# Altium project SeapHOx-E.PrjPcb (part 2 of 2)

## Sheet Pump and Aux Ports-E.SchDoc: SeapHOx ARM Controller
size Letter; DocumentNumber: 1; Revision: E; SheetNumber: 7; SheetTotal: 7; PageSetup: Record=PageOptions¦CenterHorizontal=True¦CenterVertical=True¦PrintScale=0.94¦XCorrection=1.00¦YCorrection=1.00¦PrintKind=0¦BorderSize=5000000¦LeftOffset=0¦BottomOffset=0¦Orientation=2¦PaperLength=1000¦PaperWidth=1000¦Scale=100¦PaperSource=7¦PrintQuality=-4¦MediaType=1¦DitherType=10¦PrintScaleMode=1¦PaperKind=Letter¦PaperIndex=1
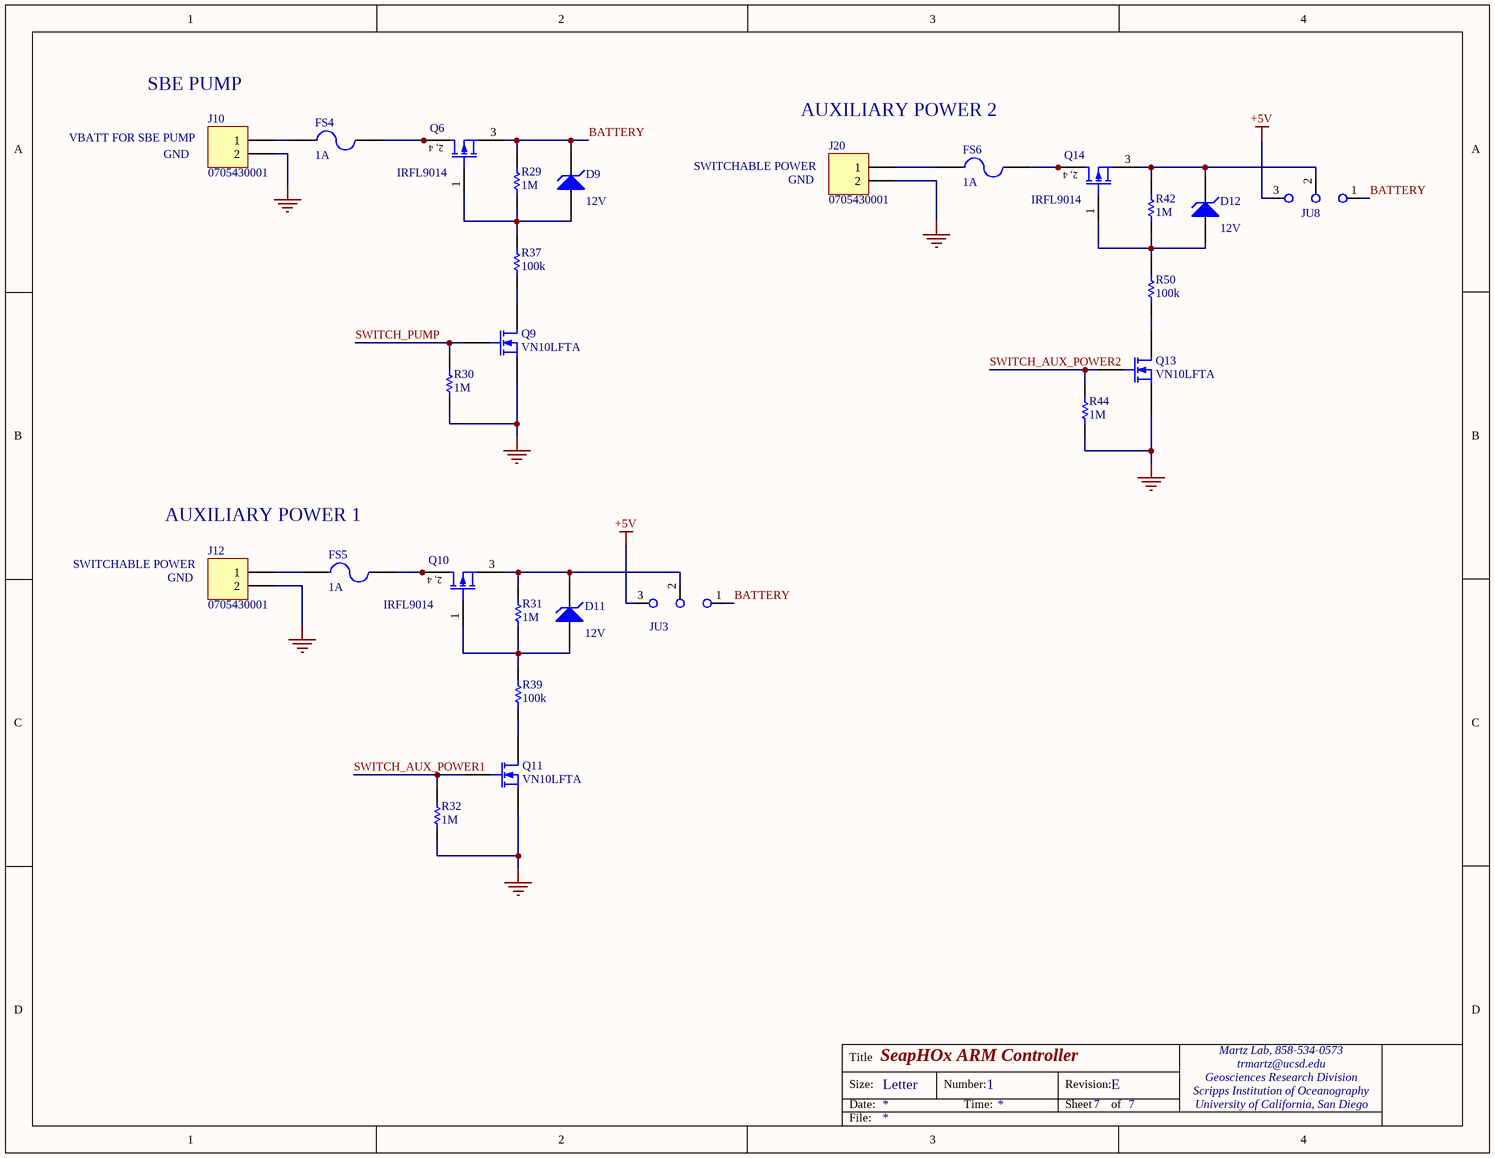
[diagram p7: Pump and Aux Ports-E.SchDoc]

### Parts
D9  12V  [SOD323F 1005]
D11  12V  [SOD323F 1005]
D12  12V  [SOD323F 1005]
FS4  Current Rating: 1A  [FUSE-NANO-SMD]  (hidden comment: 5A)
FS5  Current Rating: 1A  [FUSE-NANO-SMD]  (hidden comment: 5A)
FS6  Current Rating: 1A  [FUSE-NANO-SMD]  (hidden comment: 5A)
J10  0705430001  [70543-0001]
J12  0705430001  [70543-0001]
J20  0705430001  [70543-0001]
JU3  68000-203HLF  [Jump-3 100mil]  (value not drawn)
JU8  68000-203HLF  [Jump-3 100mil]  (value not drawn)
Q6  IRFL9014  [SOT-223]
Q9  VN10LFTA  [SOT23-3]
Q10  IRFL9014  [SOT-223]
Q11  VN10LFTA  [SOT23-3]
Q13  VN10LFTA  [SOT23-3]
Q14  IRFL9014  [SOT-223]
R29  Resistance (Ohms): 1M  [RESC0805(2012)_N]  (hidden comment: ERJ-6GEYJ105V)
R30  Resistance (Ohms): 1M  [RESC0805(2012)_N]  (hidden comment: ERJ-6GEYJ105V)
R31  Resistance (Ohms): 1M  [RESC0805(2012)_N]  (hidden comment: ERJ-6GEYJ105V)
R32  Resistance (Ohms): 1M  [RESC0805(2012)_N]  (hidden comment: ERJ-6GEYJ105V)
R37  Resistance (Ohms): 100k  [RESC0805(2012)_N]  (hidden comment: ERJ-6GEYJ104V)
R39  Resistance (Ohms): 100k  [RESC0805(2012)_N]  (hidden comment: ERJ-6GEYJ104V)
R42  Resistance (Ohms): 1M  [RESC0805(2012)_N]  (hidden comment: ERJ-6GEYJ105V)
R44  Resistance (Ohms): 1M  [RESC0805(2012)_N]  (hidden comment: ERJ-6GEYJ105V)
R50  Resistance (Ohms): 100k  [RESC0805(2012)_N]  (hidden comment: ERJ-6GEYJ104V)

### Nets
+5V: JU3.3(C3) JU8.3(C3)
BATTERY: D9.2(K) JU3.1(C1) JU8.1(C1) Q6.3(S) R29.2
GND: J10.2 J12.2 J20.2 Q9.2(S) Q11.2(S) Q13.2(S) R30.1 R32.1 R44.1
SWITCH_AUX_POWER1: Q11.1(G) R32.2
SWITCH_AUX_POWER2: Q13.1(G) R44.2
SWITCH_PUMP: Q9.1(G) R30.2
NetD9_1: D9.1(A) Q6.1(G) R29.1 R37.2
NetD11_1: D11.1(A) Q10.1(G) R31.1 R39.2
NetD11_2: D11.2(K) JU3.2(C2) Q10.3(S) R31.2
NetD12_1: D12.1(A) Q14.1(G) R42.1 R50.2
NetD12_2: D12.2(K) JU8.2(C2) Q14.3(S) R42.2
NetFS4_1: FS4.1 J10.1
NetFS4_2: FS4.2 Q6.2(D) Q6.4(D)
NetFS5_1: FS5.1 J12.1
NetFS5_2: FS5.2 Q10.2(D) Q10.4(D)
NetFS6_1: FS6.1 J20.1
NetFS6_2: FS6.2 Q14.2(D) Q14.4(D)
NetQ9_3: Q9.3(D) R37.1
NetQ11_3: Q11.3(D) R39.1
NetQ13_3: Q13.3(D) R50.1

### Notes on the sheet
- (near J10) SBE PUMP
- VBATT FOR SBE PUMP
- GND
- AUXILIARY POWER 2
- SWITCHABLE POWER
- AUXILIARY POWER 1

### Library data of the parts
D9 D11 D12 = CZRF52C12: DIODE ZENER 12V 200MW 1005; Manufacturer: Comchip Technology; Tolerance: ±5%; Current - Reverse Leakage @ Vr: 100nA @ 9V; Impedance (Max) (Zzt): 20 Ohm; Voltage - Forward (Vf) (Max) @ If: 900mV @ 10mA
FS4-FS6 = 0157001.DR: FUSE FAST 125VAC, 125VDC 1A SMD; Manufacturer: Littelfuse Inc; Fuse Type: Board Mount (Cartridge Style Excluded); Voltage Rating - AC: 125V; Breaking Capacity @ Rated Voltage: 50A; Melting I²t: 0.459; Approvals: cULus, PSE; DC Cold Resistance: 0.1537 Ohm
J10 J12 J20 = 0705430001: CONN HEADER 2POS .100 VERT GOLD; Manufacturer: Molex Inc; Connector Type: Header, Shrouded; Number of Positions: 2; Number of Positions Loaded: All; Pitch: 0.100" (2.54mm)
JU3 JU8 = 68000-203HLF: BERGSTIK II .100" SR STRAIGHT; Manufacturer: FCI; Connector Type: Header, Unshrouded; Number of Positions: 3; Number of Positions Loaded: All; Pitch: 0.100" (2.54mm)
Q6 Q10 Q14 = IRFL9014TRPBF: MOSFET P-CH 60V 1.8A SOT223; Manufacturer: Vishay Siliconix; FET Type: MOSFET P-Channel, Metal Oxide; FET Feature: Standard; Current - Continuous Drain (Id) @ 25° C: 1.8A (Tc); Rds On (Max) @ Id, Vgs: 500 mOhm @ 1.1A, 10V; Vgs(th) (Max) @ Id: 4V @ 250µA; Gate Charge (Qg) @ Vgs: 12nC @ 10V; Input Capacitance (Ciss) @ Vds: 270pF @ 25V; Power - Max: 2W
Q9 Q11 Q13 = VN10LFTA: MOSFET N-CH 60V 150MA SOT23-3; Manufacturer: Diodes Inc; FET Type: MOSFET N-Channel, Metal Oxide; FET Feature: Standard; Current - Continuous Drain (Id) @ 25° C: 150mA (Ta); Rds On (Max) @ Id, Vgs: 5 Ohm @ 500mA, 10V; Vgs(th) (Max) @ Id: 2.5V @ 1mA; Input Capacitance (Ciss) @ Vds: 60pF @ 25V; Power - Max: 330mW
R29-R32 R42 R44 = ERJ-6GEYJ105V: RES 1M OHM 1/8W 5% 0805 SMD; Manufacturer: Panasonic Electronic Components; Power (Watts): 0.125W, 1/8W; Temperature Coefficient: ±200ppm/°C
R37 R39 R50 = ERJ-6GEYJ104V: RES 100K OHM 1/8W 5% 0805 SMD; Manufacturer: Panasonic Electronic Components; Power (Watts): 0.125W, 1/8W; Temperature Coefficient: ±200ppm/°C

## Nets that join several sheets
+2.5V: Cortex Power and Voltage Regulators-E (C64.1 U18.8 U24.5), Main Non-Isolated ADC-E (R34.2)
+3.3V: Cortex Power and Voltage Regulators-E (34 pins), Cortex Signal-E (9 pins), RS232 and Perif Sensors-E (7 pins), Main Non-Isolated ADC-E (8 pins)
+3.3V_Optoisolator: Cortex Power and Voltage Regulators-E (C65.1 U26.1), Isolated Circuits-E (5 pins)
+5V: Cortex Power and Voltage Regulators-E (7 pins), RS232 and Perif Sensors-E (Q4.3 R22.2), Isolated Power Circuits-E (JU1.1 JU2.1), Main Non-Isolated ADC-E (Q12.3 R26.2), Pump and Aux Ports-E (JU3.3 JU8.3)
-2.5V: Cortex Power and Voltage Regulators-E (C63.2 U18.5), Main Non-Isolated ADC-E (R33.2)
BATTERY: Cortex Power and Voltage Regulators-E (6 pins), Cortex Signal-E (J22.1 J22.2), RS232 and Perif Sensors-E (D10.2 Q8.3 R19.2), Isolated Power Circuits-E (JU4.1), Main Non-Isolated ADC-E (R14.2), Pump and Aux Ports-E (5 pins)
GND: Cortex Power and Voltage Regulators-E (68 pins), Cortex Signal-E (12 pins), Isolated Circuits-E (8 pins), RS232 and Perif Sensors-E (24 pins), Isolated Power Circuits-E (7 pins), Main Non-Isolated ADC-E (25 pins), Pump and Aux Ports-E (9 pins)
ISO +2.5V: Isolated Circuits-E (R3.2), Isolated Power Circuits-E (C47.1 U10.5 U13.8)
ISO +3.3V: Isolated Circuits-E (13 pins), Isolated Power Circuits-E (C29.1 U10.1 U10.3 U22.1)
ISO +3.75V: Isolated Circuits-E (C35.2 J5.2 U19.7), Isolated Power Circuits-E (C40.1 U12.8 U21.1 U21.2)
ISO -2.5V: Isolated Circuits-E (R12.2), Isolated Power Circuits-E (C37.2 U13.5)
ISO -3.75V: Isolated Circuits-E (C39.2 J5.1 U19.4), Isolated Power Circuits-E (C38.2 U12.5)
ISO_GND: Isolated Circuits-E (28 pins), Isolated Power Circuits-E (26 pins)
ADS1248iso_DRDY: Cortex Signal-E (U31.119), Isolated Circuits-E (U29.6)
ADS1248iso_PWR_ON: Cortex Signal-E (U31.18), Isolated Circuits-E (R1.1)
ADS1248iso_RESET: Cortex Signal-E (U31.70), Isolated Circuits-E (R59.1)
ADS1248iso_START: Cortex Signal-E (U31.69), Isolated Circuits-E (R56.1)
ADS1248noniso_DRDY: Cortex Signal-E (U31.60), Main Non-Isolated ADC-E (U7.25)
ADS1248noniso_RESET: Cortex Signal-E (U31.59), Main Non-Isolated ADC-E (R49.1 U15.3)
ADS1248noniso_START: Cortex Signal-E (U31.68), Main Non-Isolated ADC-E (R48.1 U7.23)
ARM_RESET: Cortex Power and Voltage Regulators-E (C61.2 R58.1 SW3.2 U31.90), Cortex Signal-E (J11.10), RS232 and Perif Sensors-E (J3.3)
COM1_ON: Cortex Signal-E (U31.19), RS232 and Perif Sensors-E (U20.20)
COM2_ON: Cortex Signal-E (U31.112), RS232 and Perif Sensors-E (U23.20)
CONSOLE_ON: Cortex Signal-E (U31.108), RS232 and Perif Sensors-E (U30.20)
ISO_BAT_VOLT: Isolated Circuits-E (U3.14), Isolated Power Circuits-E (C34.2 R6.1 R27.2)
ISO_PWR_ON: Isolated Circuits-E (U1.4), Isolated Power Circuits-E (Q1.1 R4.2)
RSRXD: Cortex Power and Voltage Regulators-E (R54.2 R55.2), RS232 and Perif Sensors-E (J3.1 U30.16)
SSI1CLK: Cortex Signal-E (U31.64), Main Non-Isolated ADC-E (R53.1)
SSI1Fss: Cortex Signal-E (U31.65), Main Non-Isolated ADC-E (R47.1 U7.24)
SSI1Rx: Cortex Signal-E (U31.3), Main Non-Isolated ADC-E (U7.26)
SSI1Tx: Cortex Signal-E (U31.63), Main Non-Isolated ADC-E (U7.27)
SSI3CLK: Cortex Signal-E (U31.32), Isolated Circuits-E (U6.2)
SSI3Fss: Cortex Signal-E (U31.31), Isolated Circuits-E (U14.2)
SSI3Rx: Cortex Signal-E (U31.28), Isolated Circuits-E (U8.6)
SSI3Tx: Cortex Signal-E (U31.27), Isolated Circuits-E (U11.2)
SWITCH_2.5V: Cortex Power and Voltage Regulators-E (U24.3), Cortex Signal-E (U31.85)
SWITCH_AUX_POWER1: Cortex Signal-E (U31.141), Pump and Aux Ports-E (Q11.1 R32.2)
SWITCH_AUX_POWER2: Cortex Signal-E (U31.95), Pump and Aux Ports-E (Q13.1 R44.2)
SWITCH_MCAT: Cortex Signal-E (U31.1), RS232 and Perif Sensors-E (Q3.1 R20.2)
SWITCH_OPTODE: Cortex Signal-E (U31.2), RS232 and Perif Sensors-E (Q5.1 R25.2)
SWITCH_OPTOISO: Cortex Power and Voltage Regulators-E (U26.5), Cortex Signal-E (U31.71)
SWITCH_PRESSURE: Cortex Signal-E (U31.84), Main Non-Isolated ADC-E (Q7.1 R28.2)
SWITCH_PUMP: Cortex Signal-E (U31.4), Pump and Aux Ports-E (Q9.1 R30.2)
U0Rx: Cortex Signal-E (U31.37), RS232 and Perif Sensors-E (U30.15)
U0Tx: Cortex Signal-E (U31.38), RS232 and Perif Sensors-E (U30.13)
U2Rx (AUX1): Cortex Signal-E (U31.51), RS232 and Perif Sensors-E (U23.15)
U2Tx (AUX1): Cortex Signal-E (U31.50), RS232 and Perif Sensors-E (U23.13)
U3Rx (OPTODE): Cortex Signal-E (U31.34), RS232 and Perif Sensors-E (U20.10)
U3Tx (OPTODE): Cortex Signal-E (U31.33), RS232 and Perif Sensors-E (U20.12)
U4Rx (MCAT): Cortex Signal-E (U31.36), RS232 and Perif Sensors-E (U20.15)
U4Tx (MCAT): Cortex Signal-E (U31.35), RS232 and Perif Sensors-E (U20.13)
U5Rx (AUX2): Cortex Signal-E (U31.122), RS232 and Perif Sensors-E (U23.10)
U5Tx (AUX2): Cortex Signal-E (U31.123), RS232 and Perif Sensors-E (U23.12)
WAKE: Cortex Power and Voltage Regulators-E (5 pins), RS232 and Perif Sensors-E (J3.4)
